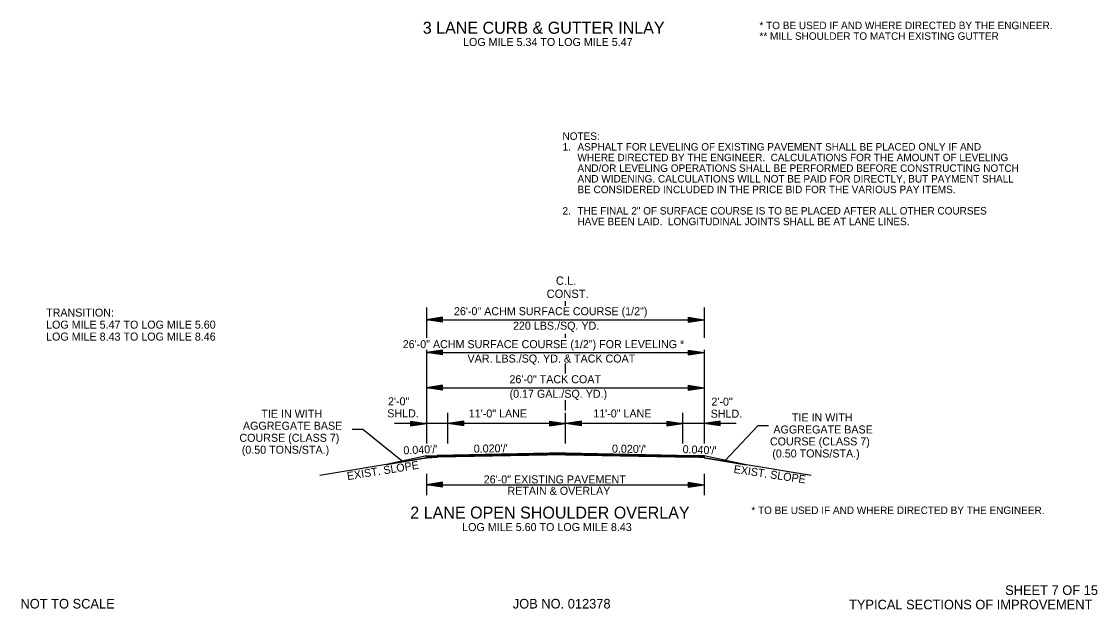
# Model space of a CAD drawing. Extents: x 542112 to 1930787, y -1968972 to 596640.
# Drawn here: x 546486 to 547494, y -1949550 to -1948999 of the extents above; entities that cross this region are included whole.
import ezdxf

# ---------------------------------------------------------------- set-up
doc = ezdxf.new("R2010")
doc.units = 0
for name, color, linetype in [('R_Border Notes', 7, 'Continuous'), ('R_Border Prem', 7, 'Continuous'), ('R_Draft', 7, 'Continuous')]:
    doc.layers.add(name, color=color, linetype=linetype)

msp = doc.modelspace()

# ---------------------------------------------------------------- linework, layer by layer
at = {"layer": 'R_Draft'}
for p, q in [((546995.7, -1949265), (546995.7, -1949260.6)), ((546865.7, -1949266.8), (546865.7, -1949295.2)), ((546880.7, -1949275.8), (546865.7, -1949278.1)), ((546865.7, -1949278.1), (547125.7, -1949278.1)), ((546880.7, -1949280.3), (546865.7, -1949278.1)), ((546880.7, -1949276.2), (546868.2, -1949278.1)), ((546880.7, -1949280), (546868.2, -1949278.1)), ((546880.7, -1949276.6), (546870.8, -1949278.1)), ((546880.7, -1949279.6), (546870.8, -1949278.1)), ((546880.7, -1949277), (546873.3, -1949278.1)), ((546880.7, -1949279.2), (546873.3, -1949278.1)), ((546880.7, -1949277.3), (546875.9, -1949278.1)), ((546880.7, -1949278.8), (546875.9, -1949278.1)), ((546880.7, -1949277.7), (546878.4, -1949278.1)), ((546880.7, -1949278.4), (546878.4, -1949278.1)), ((546880.7, -1949280.3), (546880.7, -1949275.8)), ((547110.7, -1949275.8), (547125.7, -1949278.1)), ((547110.7, -1949275.8), (547110.7, -1949280.3)), ((547110.7, -1949276.2), (547123.2, -1949278.1)), ((547110.7, -1949276.6), (547120.7, -1949278.1)), ((547110.7, -1949277), (547118.2, -1949278.1)), ((547110.7, -1949277.4), (547115.6, -1949278.1)), ((547110.7, -1949277.7), (547113.1, -1949278.1)), ((547110.7, -1949280.3), (547125.7, -1949278.1)), ((547110.7, -1949278.8), (547115.6, -1949278.1)), ((547110.7, -1949279.6), (547120.7, -1949278.1)), ((547110.7, -1949280), (547123.2, -1949278.1)), ((547110.7, -1949279.2), (547118.2, -1949278.1)), ((547110.7, -1949278.4), (547113.1, -1949278.1)), ((546995.7, -1949295.1), (546995.7, -1949291.4)), ((546865.7, -1949306.5), (546865.7, -1949394.2)), ((546880.7, -1949306.7), (546865.7, -1949308.9)), ((546865.7, -1949308.9), (547125.7, -1949308.9)), ((546880.7, -1949311.2), (546865.7, -1949308.9)), ((546880.7, -1949307.1), (546868.2, -1949308.9)), ((546880.7, -1949310.8), (546868.2, -1949308.9)), ((546880.7, -1949307.5), (546870.8, -1949308.9)), ((546880.7, -1949310.4), (546870.8, -1949308.9)), ((546880.7, -1949307.8), (546873.3, -1949308.9)), ((546880.7, -1949310.1), (546873.3, -1949308.9)), ((546880.7, -1949308.2), (546875.9, -1949308.9)), ((546880.7, -1949309.7), (546875.9, -1949308.9)), ((546880.7, -1949308.6), (546878.4, -1949308.9)), ((546880.7, -1949309.3), (546878.4, -1949308.9)), ((546880.7, -1949311.2), (546880.7, -1949306.7)), ((547110.7, -1949306.7), (547125.7, -1949308.9)), ((547110.7, -1949306.7), (547110.7, -1949311.2)), ((547110.7, -1949307.1), (547123.2, -1949308.9)), ((547110.7, -1949307.5), (547120.7, -1949308.9)), ((547110.7, -1949307.8), (547118.2, -1949308.9)), ((547110.7, -1949308.2), (547115.6, -1949308.9)), ((547110.7, -1949308.6), (547113.1, -1949308.9)), ((547110.7, -1949311.2), (547125.7, -1949308.9)), ((547110.7, -1949309.7), (547115.6, -1949308.9)), ((547110.7, -1949310.4), (547120.7, -1949308.9)), ((547110.7, -1949310.8), (547123.2, -1949308.9)), ((547110.7, -1949310.1), (547118.2, -1949308.9)), ((547110.7, -1949309.3), (547113.1, -1949308.9)), ((546995.7, -1949328.5), (546995.7, -1949319.2)), ((546880.7, -1949339.6), (546865.7, -1949341.9)), ((546865.7, -1949341.9), (547125.7, -1949341.9)), ((546880.7, -1949344.1), (546865.7, -1949341.9)), ((546880.7, -1949340), (546868.2, -1949341.9)), ((546880.7, -1949343.8), (546868.2, -1949341.9)), ((546880.7, -1949340.4), (546870.8, -1949341.9)), ((546880.7, -1949343.4), (546870.8, -1949341.9)), ((546880.7, -1949340.8), (546873.3, -1949341.9)), ((546880.7, -1949343), (546873.3, -1949341.9)), ((546880.7, -1949341.1), (546875.9, -1949341.9)), ((546880.7, -1949342.6), (546875.9, -1949341.9)), ((546880.7, -1949341.5), (546878.4, -1949341.9)), ((546880.7, -1949342.2), (546878.4, -1949341.9)), ((546880.7, -1949344.1), (546880.7, -1949339.6)), ((547110.7, -1949339.6), (547125.7, -1949341.9)), ((547110.7, -1949339.6), (547110.7, -1949344.1)), ((547110.7, -1949340), (547123.2, -1949341.9)), ((547110.7, -1949340.4), (547120.7, -1949341.9)), ((547110.7, -1949340.8), (547118.2, -1949341.9)), ((547110.7, -1949341.1), (547115.6, -1949341.9)), ((547110.7, -1949341.5), (547113.1, -1949341.9)), ((547110.7, -1949344.1), (547125.7, -1949341.9)), ((547110.7, -1949342.6), (547115.6, -1949341.9)), ((547110.7, -1949343.4), (547120.7, -1949341.9)), ((547110.7, -1949343.8), (547123.2, -1949341.9)), ((547110.7, -1949343), (547118.2, -1949341.9)), ((547110.7, -1949342.2), (547113.1, -1949341.9)), ((546995.7, -1949363.4), (546995.7, -1949353.5)), ((546885.7, -1949394.2), (546885.7, -1949365.5)), ((546995.7, -1949394.1), (546995.7, -1949365.5)), ((547105.7, -1949394.1), (547105.7, -1949365.5)), ((546865.7, -1949375.4), (546835.7, -1949375.4)), ((546850.7, -1949373.2), (546865.7, -1949375.4)), ((546850.7, -1949373.2), (546850.7, -1949377.7)), ((546850.7, -1949373.5), (546863.2, -1949375.4)), ((546850.7, -1949373.9), (546860.7, -1949375.4)), ((546850.7, -1949374.3), (546858.2, -1949375.4)), ((546850.7, -1949374.7), (546855.6, -1949375.4)), ((546850.7, -1949375.1), (546853.1, -1949375.4)), ((546850.7, -1949377.7), (546865.7, -1949375.4)), ((546850.7, -1949376.1), (546855.6, -1949375.4)), ((546850.7, -1949376.9), (546860.7, -1949375.4)), ((546850.7, -1949377.3), (546863.2, -1949375.4)), ((546850.7, -1949376.5), (546858.2, -1949375.4)), ((546850.7, -1949375.8), (546853.1, -1949375.4)), ((546885.7, -1949375.4), (546865.7, -1949375.4)), ((546900.7, -1949373.2), (546885.7, -1949375.4)), ((546995.7, -1949375.4), (546885.7, -1949375.4)), ((546900.7, -1949377.7), (546885.7, -1949375.4)), ((546900.7, -1949373.5), (546888.2, -1949375.4)), ((546900.7, -1949377.3), (546888.2, -1949375.4)), ((546900.7, -1949373.9), (546890.8, -1949375.4)), ((546900.7, -1949376.9), (546890.8, -1949375.4)), ((546900.7, -1949374.3), (546893.3, -1949375.4)), ((546900.7, -1949376.5), (546893.3, -1949375.4)), ((546900.7, -1949374.7), (546895.9, -1949375.4)), ((546900.7, -1949376.1), (546895.9, -1949375.4)), ((546900.7, -1949375.1), (546898.4, -1949375.4)), ((546900.7, -1949375.8), (546898.4, -1949375.4)), ((546900.7, -1949377.7), (546900.7, -1949373.2)), ((546980.7, -1949373.2), (546995.7, -1949375.4)), ((546980.7, -1949373.2), (546980.7, -1949377.7)), ((546980.7, -1949373.5), (546993.2, -1949375.4)), ((546980.7, -1949373.9), (546990.7, -1949375.4)), ((546980.7, -1949374.3), (546988.2, -1949375.4)), ((546980.7, -1949374.7), (546985.6, -1949375.4)), ((546980.7, -1949375.1), (546983.1, -1949375.4)), ((546980.7, -1949377.7), (546995.7, -1949375.4)), ((546980.7, -1949376.1), (546985.6, -1949375.4)), ((546980.7, -1949376.9), (546990.7, -1949375.4)), ((546980.7, -1949377.3), (546993.2, -1949375.4)), ((546980.7, -1949376.5), (546988.2, -1949375.4)), ((546980.7, -1949375.8), (546983.1, -1949375.4)), ((547010.7, -1949373.2), (546995.7, -1949375.4)), ((547105.7, -1949375.4), (546995.7, -1949375.4)), ((547010.7, -1949377.7), (546995.7, -1949375.4)), ((547010.7, -1949373.5), (546998.2, -1949375.4)), ((547010.7, -1949377.3), (546998.2, -1949375.4)), ((547010.7, -1949373.9), (547000.8, -1949375.4)), ((547010.7, -1949376.9), (547000.8, -1949375.4)), ((547010.7, -1949374.3), (547003.3, -1949375.4)), ((547010.7, -1949376.5), (547003.3, -1949375.4)), ((547010.7, -1949374.7), (547005.9, -1949375.4)), ((547010.7, -1949376.1), (547005.9, -1949375.4)), ((547010.7, -1949375.1), (547008.4, -1949375.4)), ((547010.7, -1949375.8), (547008.4, -1949375.4)), ((547010.7, -1949377.7), (547010.7, -1949373.2)), ((547090.7, -1949373.2), (547105.7, -1949375.4)), ((547090.7, -1949373.2), (547090.7, -1949377.7)), ((547090.7, -1949373.5), (547103.2, -1949375.4)), ((547090.7, -1949373.9), (547100.7, -1949375.4)), ((547090.7, -1949374.3), (547098.2, -1949375.4)), ((547090.7, -1949374.7), (547095.6, -1949375.4)), ((547090.7, -1949375.1), (547093.1, -1949375.4)), ((547090.7, -1949377.7), (547105.7, -1949375.4)), ((547090.7, -1949376.1), (547095.6, -1949375.4)), ((547090.7, -1949376.9), (547100.7, -1949375.4)), ((547090.7, -1949377.3), (547103.2, -1949375.4)), ((547090.7, -1949376.5), (547098.2, -1949375.4)), ((547090.7, -1949375.8), (547093.1, -1949375.4)), ((547125.7, -1949375.4), (547105.7, -1949375.4)), ((547140.7, -1949373.2), (547125.7, -1949375.4)), ((547155.7, -1949375.4), (547125.7, -1949375.4)), ((547140.7, -1949377.7), (547125.7, -1949375.4)), ((547140.7, -1949373.5), (547128.2, -1949375.4)), ((547140.7, -1949377.3), (547128.2, -1949375.4)), ((547140.7, -1949373.9), (547130.8, -1949375.4)), ((547140.7, -1949376.9), (547130.8, -1949375.4)), ((547140.7, -1949374.3), (547133.3, -1949375.4)), ((547140.7, -1949376.5), (547133.3, -1949375.4)), ((547140.7, -1949374.7), (547135.9, -1949375.4)), ((547140.7, -1949376.1), (547135.9, -1949375.4)), ((547140.7, -1949375.1), (547138.4, -1949375.4)), ((547140.7, -1949375.8), (547138.4, -1949375.4)), ((547140.7, -1949377.7), (547140.7, -1949373.2)), ((546865.7, -1949405.8), (546828.2, -1949413.8)), ((546865.7, -1949405.8), (546875.7, -1949405.4)), ((546865.7, -1949406.1), (546875.8, -1949405.7)), ((546865.7, -1949407.5), (546865.7, -1949405.8)), ((546865.7, -1949407.5), (546865.7, -1949405.8)), ((546865.7, -1949407.5), (546865.7, -1949405.8)), ((546865.7, -1949406.4), (546875.8, -1949406)), ((546865.7, -1949406.7), (546875.8, -1949406.3)), ((546865.7, -1949407), (546875.8, -1949406.6)), ((546995.7, -1949403), (546875.7, -1949405.4)), ((546995.7, -1949403.3), (546875.7, -1949405.7)), ((546995.8, -1949403.6), (546875.8, -1949406)), ((546995.8, -1949403.9), (546875.8, -1949406.3)), ((546995.8, -1949404.2), (546875.8, -1949406.6)), ((546995.8, -1949404.5), (546875.8, -1949406.9)), ((546995.8, -1949404.7), (546875.8, -1949407.1)), ((546995.7, -1949403), (547115.7, -1949405.4)), ((546995.7, -1949403.3), (547115.7, -1949405.7)), ((546995.7, -1949403.6), (547115.7, -1949406)), ((546995.7, -1949403.9), (547115.7, -1949406.3)), ((546995.7, -1949404.2), (547115.7, -1949406.6)), ((546995.7, -1949404.5), (547115.7, -1949406.9)), ((546995.7, -1949404.7), (547115.7, -1949407.1)), ((547125.7, -1949405.8), (547115.7, -1949405.4)), ((547125.7, -1949406.1), (547115.7, -1949405.7)), ((547125.7, -1949406.4), (547115.7, -1949406)), ((547125.7, -1949406.7), (547115.7, -1949406.3)), ((547125.7, -1949407), (547115.7, -1949406.6)), ((547125.7, -1949407.5), (547125.7, -1949405.8)), ((547125.7, -1949405.8), (547125.7, -1949407.5)), ((547165, -1949414.1), (547125.7, -1949405.8)), ((547125.7, -1949405.8), (547125.7, -1949407.5)), ((547125.7, -1949407.5), (547125.7, -1949405.8)), ((546865.7, -1949407.5), (546765.6, -1949424.2)), ((546828.2, -1949413.8), (546865.7, -1949407.5)), ((546865.7, -1949407.3), (546875.8, -1949406.9)), ((546865.7, -1949407.5), (546875.8, -1949407.1)), ((546865.7, -1949407.5), (546865.7, -1949407.5)), ((547125.7, -1949407.3), (547115.7, -1949406.9)), ((547125.7, -1949407.5), (547115.7, -1949407.1)), ((547225.8, -1949424.2), (547125.7, -1949407.5)), ((547125.7, -1949407.5), (547125.7, -1949407.5)), ((547125.7, -1949407.5), (547165, -1949414.1)), ((546865.7, -1949422.6), (546865.7, -1949442.6)), ((547125.7, -1949422.6), (547125.7, -1949442.6)), ((546880.7, -1949430.6), (546865.7, -1949432.9)), ((546865.7, -1949432.9), (547125.7, -1949432.9)), ((546880.7, -1949435.1), (546865.7, -1949432.9)), ((546880.7, -1949431), (546868.2, -1949432.9)), ((546880.7, -1949434.8), (546868.2, -1949432.9)), ((546880.7, -1949431.4), (546870.8, -1949432.9)), ((546880.7, -1949434.4), (546870.8, -1949432.9)), ((546880.7, -1949431.8), (546873.3, -1949432.9)), ((546880.7, -1949434), (546873.3, -1949432.9)), ((546880.7, -1949432.1), (546875.9, -1949432.9)), ((546880.7, -1949433.6), (546875.9, -1949432.9)), ((546880.7, -1949432.5), (546878.4, -1949432.9)), ((546880.7, -1949433.2), (546878.4, -1949432.9)), ((546880.7, -1949435.1), (546880.7, -1949430.6)), ((547110.7, -1949430.6), (547125.7, -1949432.9)), ((547110.7, -1949430.6), (547110.7, -1949435.1)), ((547110.7, -1949431), (547123.2, -1949432.9)), ((547110.7, -1949431.4), (547120.7, -1949432.9)), ((547110.7, -1949431.8), (547118.2, -1949432.9)), ((547110.7, -1949432.2), (547115.6, -1949432.9)), ((547110.7, -1949432.5), (547113.1, -1949432.9)), ((547110.7, -1949435.1), (547125.7, -1949432.9)), ((547110.7, -1949433.6), (547115.6, -1949432.9)), ((547110.7, -1949434.4), (547120.7, -1949432.9)), ((547110.7, -1949434.8), (547123.2, -1949432.9)), ((547110.7, -1949434), (547118.2, -1949432.9)), ((547110.7, -1949433.2), (547113.1, -1949432.9))]:
    msp.add_line(p, q, dxfattribs=at)
for points in [[(547125.7, -1949266.8), (547125.7, -1949295.2)], [(547125.7, -1949306.5), (547125.7, -1949394.1)], [(546796, -1949380.8), (546806, -1949380.8), (546843.1, -1949410.7)], [(547185.9, -1949377.6), (547175.9, -1949377.6), (547145.4, -1949410.1)]]:
    msp.add_lwpolyline(points, dxfattribs=at)

# ---------------------------------------------------------------- texts
at = {"layer": 'R_Border Notes'}
for s, height, p in [('NOTES: ', 7, (546993, -1949109.5)), ('1.', 7, (546993, -1949119.5)), ('ASPHALT FOR LEVELING OF EXISTING PAVEMENT SHALL BE PLACED ONLY IF AND', 7, (547007, -1949119.5)), ('WHERE DIRECTED BY THE ENGINEER.  CALCULATIONS FOR THE AMOUNT OF LEVELING', 7, (547007, -1949129.5)), ('AND/OR LEVELING OPERATIONS SHALL BE PERFORMED BEFORE CONSTRUCTING NOTCH', 7, (547007, -1949139.5)), ('AND WIDENING. CALCULATIONS WILL NOT BE PAID FOR DIRECTLY, BUT PAYMENT SHALL', 7, (547007, -1949149.5)), ('BE CONSIDERED INCLUDED IN THE PRICE BID FOR THE VARIOUS PAY ITEMS.', 7, (547007, -1949159.5)), ('2.', 7, (546993, -1949179.5)), ('THE FINAL 2" OF SURFACE COURSE IS TO BE PLACED AFTER ALL OTHER COURSES', 7, (547007, -1949179.5)), ('HAVE BEEN LAID.  LONGITUDINAL JOINTS SHALL BE AT LANE LINES.', 7, (547007, -1949189.5)), ('SHEET 7 OF 15', 9, (547407.7, -1949536.2)), ('NOT TO SCALE', 9, (546485.2, -1949548.9)), ('TYPICAL SECTIONS OF IMPROVEMENT', 9, (547261.4, -1949549.7))]:
    msp.add_text(s, height=height, dxfattribs=at).set_placement(p)
msp.add_text('JOB NO. 012378', height=9, rotation=360, dxfattribs=at).set_placement((546946.4, -1949548.9))
at = {"layer": 'R_Border Prem'}
for s, p in [('* TO BE USED IF AND WHERE DIRECTED BY THE ENGINEER.', (547177.5, -1949005.7)), ('** MILL SHOULDER TO MATCH EXISTING GUTTER', (547177.5, -1949015.7)), ('* TO BE USED IF AND WHERE DIRECTED BY THE ENGINEER.', (547169.9, -1949460.3))]:
    msp.add_text(s, height=7, dxfattribs=at).set_placement(p)
at = {"layer": 'R_Draft'}
for s, height, p in [('3 LANE CURB & GUTTER INLAY', 11.25, (546862.1, -1949010)), ('LOG MILE 5.34 TO LOG MILE 5.47', 7.5, (546899.8, -1949021.5)), ('C.L.', 7.8, (546986.8, -1949245.4)), ('CONST.', 7.8, (546978.1, -1949257.7)), ('TRANSITION:', 7.5, (546509.2, -1949275.2)), ('26\'-0" ACHM SURFACE COURSE (1/2")', 7.5, (546891.3, -1949273.9)), ('LOG MILE 5.47 TO LOG MILE 5.60', 7.5, (546509.2, -1949286.5)), ('220 LBS./SQ. YD. ', 7.5, (546946.6, -1949287.5)), ('LOG MILE 8.43 TO LOG MILE 8.46', 7.5, (546509.2, -1949297.7)), ('26\'-0" ACHM SURFACE COURSE (1/2") FOR LEVELING *', 7.5, (546843.3, -1949304.8)), ('VAR. LBS./SQ. YD. & TACK COAT', 7.5, (546904, -1949318.3)), ('26\'-0" TACK COAT', 7.5, (546943.3, -1949337.7)), ('(0.17 GAL./SQ. YD.)', 7.5, (546943.4, -1949351.3)), ('2\'-0"', 7.5, (546829.5, -1949358.4)), ('2\'-0"', 7.5, (547132.5, -1949358.7)), ('TIE IN WITH ', 7.5, (546710.9, -1949370.1)), ('SHLD.', 7.5, (546828.8, -1949369.7)), ('11\'-0" LANE', 7.5, (546905.2, -1949369.8)), ('11\'-0" LANE', 7.5, (547021.8, -1949369.8)), ('SHLD.', 7.5, (547131.8, -1949370)), ('TIE IN WITH ', 7.5, (547207.9, -1949373.5)), ('AGGREGATE BASE', 7.5, (546693.6, -1949381.3)), ('COURSE (CLASS 7)', 7.5, (546690.3, -1949392.6)), ('AGGREGATE BASE', 7.5, (547190.6, -1949384.8)), ('(0.50 TONS/STA.)', 7.5, (546692.5, -1949403.8)), ('COURSE (CLASS 7)', 7.5, (547187.3, -1949396)), ('(0.50 TONS/STA.)', 7.5, (547189.5, -1949407.3)), ('26\'-0" EXISTING PAVEMENT', 7.5, (546919.2, -1949431.6)), ('RETAIN & OVERLAY', 7.5, (546941.4, -1949442.3)), ('2 LANE OPEN SHOULDER OVERLAY', 11.25, (546850.4, -1949464.6)), ('LOG MILE 5.60 TO LOG MILE 8.43', 7.5, (546899, -1949476.3))]:
    msp.add_text(s, height=height, dxfattribs=at).set_placement(p)
for s, rotation, p in [("0.040'/'", 2.448, (546844.1, -1949404.4)), ("0.020'/'", 0.8719, (546909.9, -1949402.8)), ("0.020'/'", 359.164, (547039.3, -1949402.7)), ("0.040'/'", 357.8168, (547105.4, -1949403.2)), ('EXIST. SLOPE', 9.1534, (546791.7, -1949428.6)), ('EXIST. SLOPE', 351.5755, (547153, -1949421.7))]:
    msp.add_text(s, height=7.5, rotation=rotation, dxfattribs=at).set_placement(p)

doc.saveas('drawing.dxf')
